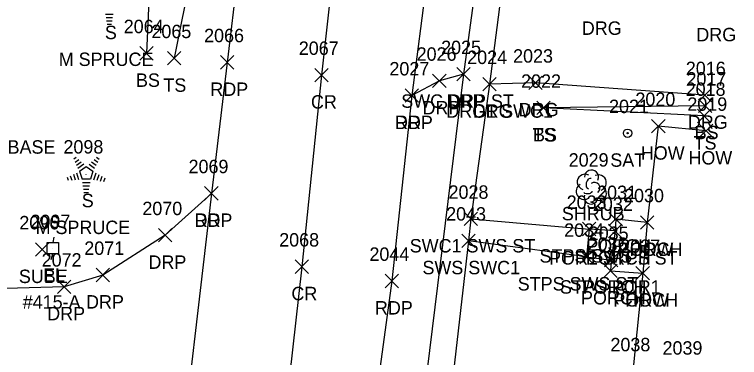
# Model space of a CAD drawing. Extents: x 1651305 to 1654558, y 539481 to 548441.
# Drawn here: x 1654335.1 to 1654443.3, y 544297.6 to 544348.7 of the extents above; entities that cross this region are included whole.
import ezdxf

# ---------------------------------------------------------------- set-up
doc = ezdxf.new("R2010")
doc.units = 0
for name, color, linetype in [('L_A', 7, 'Continuous'), ('L_C', 7, 'Continuous'), ('L_I', 7, 'Continuous'), ('L_TIC', 7, 'Continuous'), ('LANT', 7, 'Continuous'), ('LBC', 7, 'Continuous'), ('LBF', 7, 'Continuous'), ('LELB', 7, 'Continuous'), ('LSH', 7, 'Continuous'), ('LTC', 7, 'Continuous'), ('P_A', 7, 'Continuous'), ('P_I', 7, 'Continuous'), ('P_TIC', 7, 'Continuous'), ('PET', 7, 'Continuous'), ('PRC', 7, 'Continuous'), ('R_A', 7, 'Continuous'), ('R_I', 7, 'Continuous'), ('R_TIC', 7, 'Continuous'), ('RDG', 7, 'Continuous'), ('RDP', 7, 'Continuous'), ('RSW', 7, 'Continuous'), ('U_A', 7, 'Continuous'), ('U_C', 7, 'Continuous'), ('U_I', 7, 'Continuous'), ('U_TIC', 7, 'Continuous'), ('UEPT', 7, 'Continuous')]:
    doc.layers.add(name, color=color, linetype=linetype)

msp = doc.modelspace()

# ---------------------------------------------------------------- linework, layer by layer
at = {"layer": 'L_TIC'}
for points in [[(1654353.81, 544341.89), (1654355.81, 544343.89)], [(1654355.81, 544341.89), (1654353.81, 544343.89)], [(1654357.93, 544341.15), (1654359.93, 544343.15)], [(1654359.93, 544341.15), (1654357.93, 544343.15)], [(1654437.14, 544334.08), (1654439.14, 544336.08)], [(1654439.14, 544334.08), (1654437.14, 544336.08)], [(1654413.02, 544333.75), (1654415.02, 544335.75)], [(1654415.02, 544333.75), (1654413.02, 544335.75)], [(1654413.02, 544333.75), (1654415.02, 544335.75)], [(1654415.02, 544333.75), (1654413.02, 544335.75)], [(1654437.01, 544332.55), (1654439.01, 544334.55)], [(1654439.01, 544332.55), (1654437.01, 544334.55)], [(1654430.16, 544331.04), (1654432.16, 544333.04)], [(1654432.16, 544331.04), (1654430.16, 544333.04)], [(1654437.27, 544330.32), (1654439.27, 544332.32)], [(1654439.27, 544330.32), (1654437.27, 544332.32)], [(1654423.8, 544317.17), (1654425.8, 544319.17)], [(1654425.8, 544317.17), (1654423.8, 544319.17)], [(1654428.48, 544316.69), (1654430.48, 544318.69)], [(1654430.48, 544316.69), (1654428.48, 544318.69)], [(1654428.48, 544316.69), (1654430.48, 544318.69)], [(1654430.48, 544316.69), (1654428.48, 544318.69)], [(1654419.83, 544315.7), (1654421.83, 544317.7)], [(1654421.83, 544315.7), (1654419.83, 544317.7)], [(1654423.74, 544315.41), (1654425.74, 544317.41)], [(1654425.74, 544315.41), (1654423.74, 544317.41)], [(1654423.74, 544315.41), (1654425.74, 544317.41)], [(1654425.74, 544315.41), (1654423.74, 544317.41)], [(1654419.45, 544311.54), (1654421.45, 544313.54)], [(1654421.45, 544311.54), (1654419.45, 544313.54)], [(1654423.12, 544311.07), (1654425.12, 544313.07)], [(1654425.12, 544311.07), (1654423.12, 544313.07)], [(1654423.12, 544311.07), (1654425.12, 544313.07)], [(1654425.12, 544311.07), (1654423.12, 544313.07)], [(1654423.01, 544309.46), (1654425.01, 544311.46)], [(1654425.01, 544309.46), (1654423.01, 544311.46)], [(1654427.83, 544309.14), (1654429.83, 544311.14)], [(1654429.83, 544309.14), (1654427.83, 544311.14)], [(1654427.83, 544309.14), (1654429.83, 544311.14)], [(1654429.83, 544309.14), (1654427.83, 544311.14)]]:
    msp.add_lwpolyline(points, dxfattribs=at)
at = {"layer": 'LANT'}
for radius in [0.625, 0.0833]:
    msp.add_circle((1654426.58, 544330.98), radius, dxfattribs=at)
at = {"layer": 'LBC'}
msp.add_lwpolyline([(1654438.27, 544331.32), (1654431.16, 544332.04), (1654429.48, 544317.69), (1654428.83, 544310.14), (1654427.36, 544295.48), (1654435.14, 544294.98)], dxfattribs=at)
at = {"layer": 'LBF'}
for points in [[(1654429.48, 544317.69), (1654424.8, 544318.17), (1654424.74, 544316.41), (1654424.12, 544312.07), (1654424.01, 544310.46), (1654428.83, 544310.14)], [(1654424.74, 544316.41), (1654420.83, 544316.7), (1654420.45, 544312.54), (1654424.12, 544312.07)]]:
    msp.add_lwpolyline(points, dxfattribs=at)
at = {"layer": 'LELB'}
for points in [[(1654343.58, 544585.05), (1654350.34, 544565.29), (1654357.01, 544542.02), (1654364.12, 544503.19), (1654366.8, 544473.04), (1654369.36, 544432.64), (1654369.04, 544397.45), (1654364.12, 544367.94), (1654358.93, 544342.15)], [(1654331.96, 544545.97), (1654352.54, 544530.8), (1654354.98, 544503.34), (1654356.4, 544472.14), (1654357.75, 544432.79), (1654359.2, 544399.51), (1654355.94, 544368.56), (1654354.81, 544342.89)], [(1654438.14, 544335.08), (1654414.02, 544334.75)], [(1654438.01, 544333.55), (1654414.02, 544334.75)]]:
    msp.add_lwpolyline(points, dxfattribs=at)
at = {"layer": 'LSH'}
msp.add_line((1654421.14, 544323), (1654421.14, 544323), dxfattribs=at)
msp.add_line((1654421.14, 544323), (1654421.14, 544323), dxfattribs=at)
msp.add_arc((1654421.19, 544324.44), 1.05, 335.5272, 180.9563, dxfattribs=at)
for centre, major_axis, ratio, start_param, end_param in [((1654420.35, 544323.67), (1.21, -0.51), 0.895232, 1.570796, 4.712389), ((1654420.93, 544323.46), (-0.208, -0.792), 0.645439, 3.141593, 6.283185), ((1654422.18, 544323.58), (-1.14, -0.48), 0.949671, 1.570796, 4.712389), ((1654420.06, 544322.29), (0.58, -1.04), 0.959034, 3.141593, 6.283185), ((1654421.64, 544322.83), (-0.5, 0.667), 0.989748, 3.141593, 6.283185), ((1654422.14, 544322.17), (-1.09, 0.79), 0.841452, 1.570796, 4.712389), ((1654420.68, 544322.25), (-0.625, -0.083), 0.423636, 0, 3.141593), ((1654421.14, 544321.5), (0.26, 1.06), 0.942809, 1.570796, 4.712389)]:
    msp.add_ellipse(centre, major_axis=major_axis, ratio=ratio, start_param=start_param, end_param=end_param, dxfattribs=at)
at = {"layer": 'LTC'}
for p, q in [((1654349.85, 544348.67), (1654348.71, 544348.67)), ((1654349.77, 544348.17), (1654348.78, 544348.17)), ((1654349.68, 544347.67), (1654348.85, 544347.67)), ((1654349.6, 544347.17), (1654348.93, 544347.17)), ((1654343.96, 544327.16), (1654344.32, 544327.41)), ((1654347.36, 544327.4), (1654347.78, 544327.09)), ((1654344.17, 544326.69), (1654344.7, 544327.08)), ((1654344.38, 544326.23), (1654345.09, 544326.74)), ((1654344.59, 544325.76), (1654345.47, 544326.4)), ((1654346.25, 544326.35), (1654347.06, 544325.76)), ((1654346.62, 544326.7), (1654347.3, 544326.21)), ((1654346.99, 544327.05), (1654347.54, 544326.65)), ((1654344.36, 544325.09), (1654344.69, 544324.07)), ((1654344.82, 544325.31), (1654345.83, 544326.04)), ((1654344.82, 544325.31), (1654345.2, 544324.11)), ((1654345.83, 544326.04), (1654346.83, 544325.31)), ((1654346.83, 544325.31), (1654346.44, 544324.11)), ((1654347.26, 544325.04), (1654346.93, 544324)), ((1654343, 544324.44), (1654343.15, 544323.97)), ((1654343.45, 544324.65), (1654343.66, 544324)), ((1654343.91, 544324.87), (1654344.18, 544324.03)), ((1654346.44, 544324.11), (1654345.2, 544324.11)), ((1654347.71, 544324.79), (1654347.42, 544323.91)), ((1654348.15, 544324.54), (1654347.92, 544323.81)), ((1654348.6, 544324.29), (1654348.41, 544323.72)), ((1654346.4, 544323.61), (1654345.25, 544323.61)), ((1654346.31, 544323.11), (1654345.32, 544323.11)), ((1654346.23, 544322.61), (1654345.4, 544322.61)), ((1654346.15, 544322.11), (1654345.47, 544322.11))]:
    msp.add_line(p, q, dxfattribs=at)
at = {"layer": 'P_TIC'}
for points in [[(1654365.85, 544340.54), (1654367.85, 544342.54)], [(1654367.85, 544340.54), (1654365.85, 544342.54)], [(1654379.92, 544338.65), (1654381.92, 544340.65)], [(1654381.92, 544338.65), (1654379.92, 544340.65)], [(1654393.39, 544335.59), (1654395.39, 544337.59)], [(1654395.39, 544335.59), (1654393.39, 544337.59)], [(1654363.49, 544321.02), (1654365.49, 544323.02)], [(1654365.49, 544321.02), (1654363.49, 544323.02)], [(1654377, 544310.09), (1654379, 544312.09)], [(1654379, 544310.09), (1654377, 544312.09)], [(1654390.4, 544307.96), (1654392.4, 544309.96)], [(1654392.4, 544307.96), (1654390.4, 544309.96)]]:
    msp.add_lwpolyline(points, dxfattribs=at)
at = {"layer": 'PET'}
for points in [[(1654345.04, 544588.36), (1654350.59, 544607.19), (1654356.58, 544624.31), (1654366.69, 544597.7), (1654378.7, 544565.63), (1654388.8, 544536.02), (1654394.39, 544506.43), (1654399.12, 544481.01), (1654401.13, 544462.89), (1654401.53, 544436.35), (1654401.83, 544421.31), (1654397.37, 544359.7), (1654394.39, 544336.59), (1654391.4, 544308.96), (1654388.94, 544290.74), (1654386.84, 544274.06), (1654380.97, 544229.45), (1654377.75, 544202.91), (1654375.63, 544181.04), (1654372.19, 544149.75), (1654366.61, 544105.72), (1654362.8, 544072.79)], [(1654345.04, 544588.36), (1654352.84, 544566.03), (1654357.71, 544551.64), (1654360.67, 544540.21), (1654367.97, 544503.91), (1654371.19, 544473.22), (1654373.31, 544432.69), (1654372.37, 544396.63), (1654369.95, 544367.4), (1654366.85, 544341.54), (1654364.49, 544322.02), (1654359.18, 544276.5), (1654356.39, 544249.38), (1654353.63, 544216.56), (1654349.27, 544178.19), (1654347.29, 544164.71), (1654345.69, 544149.48), (1654340.92, 544117.48), (1654336.05, 544077.13)]]:
    msp.add_lwpolyline(points, dxfattribs=at)
at = {"layer": 'PRC'}
msp.add_lwpolyline([(1654350.59, 544607.19), (1654355.93, 544592.7), (1654363.68, 544570.63), (1654372.22, 544542.27), (1654380.24, 544505.39), (1654384.95, 544473.92), (1654386.82, 544433.75), (1654385.71, 544395.52), (1654383.86, 544366), (1654380.92, 544339.65), (1654378, 544311.09), (1654373.89, 544274.84), (1654369.01, 544231.01), (1654366.63, 544212.46), (1654362.44, 544177.97), (1654359.49, 544151.89), (1654354.07, 544107.93), (1654348.42, 544063.01)], dxfattribs=at)
at = {"layer": 'R_TIC'}
for points in [[(1654401.1, 544338.77), (1654403.1, 544340.77)], [(1654403.1, 544338.77), (1654401.1, 544340.77)], [(1654401.1, 544338.77), (1654403.1, 544340.77)], [(1654403.1, 544338.77), (1654401.1, 544340.77)], [(1654397.5, 544337.78), (1654399.5, 544339.78)], [(1654399.5, 544337.78), (1654397.5, 544339.78)], [(1654404.99, 544337.29), (1654406.99, 544339.29)], [(1654406.99, 544337.29), (1654404.99, 544339.29)], [(1654404.99, 544337.29), (1654406.99, 544339.29)], [(1654406.99, 544337.29), (1654404.99, 544339.29)], [(1654411.84, 544337.5), (1654413.84, 544339.5)], [(1654413.84, 544337.5), (1654411.84, 544339.5)], [(1654393.39, 544335.59), (1654395.39, 544337.59)], [(1654395.39, 544335.59), (1654393.39, 544337.59)], [(1654437.08, 544335.64), (1654439.08, 544337.64)], [(1654439.08, 544335.64), (1654437.08, 544337.64)], [(1654363.49, 544321.02), (1654365.49, 544323.02)], [(1654365.49, 544321.02), (1654363.49, 544323.02)], [(1654402.21, 544317.21), (1654404.21, 544319.21)], [(1654404.21, 544317.21), (1654402.21, 544319.21)], [(1654402.21, 544317.21), (1654404.21, 544319.21)], [(1654404.21, 544317.21), (1654402.21, 544319.21)], [(1654419.83, 544315.7), (1654421.83, 544317.7)], [(1654421.83, 544315.7), (1654419.83, 544317.7)], [(1654356.62, 544314.77), (1654358.62, 544316.77)], [(1654358.62, 544314.77), (1654356.62, 544316.77)], [(1654401.85, 544313.96), (1654403.85, 544315.96)], [(1654403.85, 544313.96), (1654401.85, 544315.96)], [(1654401.85, 544313.96), (1654403.85, 544315.96)], [(1654403.85, 544313.96), (1654401.85, 544315.96)], [(1654419.45, 544311.54), (1654421.45, 544313.54)], [(1654421.45, 544311.54), (1654419.45, 544313.54)], [(1654347.31, 544308.85), (1654349.31, 544310.85)], [(1654349.31, 544308.85), (1654347.31, 544310.85)], [(1654341.52, 544307.1), (1654343.52, 544309.1)], [(1654343.52, 544307.1), (1654341.52, 544309.1)]]:
    msp.add_lwpolyline(points, dxfattribs=at)
at = {"layer": 'RDG'}
msp.add_lwpolyline([(1654438.08, 544336.64), (1654412.84, 544338.5), (1654405.99, 544338.29)], dxfattribs=at)
at = {"layer": 'RDP'}
for points in [[(1654402.1, 544339.77), (1654398.5, 544338.78), (1654394.39, 544336.59)], [(1654364.49, 544322.02), (1654357.62, 544315.77), (1654348.31, 544309.85), (1654342.52, 544308.1), (1654304.14, 544306.98), (1654288.67, 544307.62)]]:
    msp.add_lwpolyline(points, dxfattribs=at)
at = {"layer": 'RSW'}
for points in [[(1654407.4, 544661.78), (1654407.29, 544658.87), (1654407.96, 544657.88), (1654443.27, 544654.59), (1654438.81, 544619.89), (1654433.56, 544580.17), (1654430.14, 544553.99), (1654428.03, 544537.28), (1654424.83, 544512.84), (1654419.77, 544473.61), (1654412.66, 544419.66), (1654404.12, 544354.77), (1654402.1, 544339.77), (1654395.49, 544286.06), (1654394.01, 544276.12), (1654388.39, 544229.58), (1654383.89, 544196.38), (1654382.2, 544184.33), (1654378.35, 544149.15), (1654372.36, 544105.49), (1654368.55, 544072.05)], [(1654433.77, 544447.32), (1654420.39, 544448.73), (1654416.3, 544419.47), (1654415.22, 544408.68), (1654412.66, 544388.62), (1654423.02, 544387.52), (1654429.58, 544386.83), (1654429.1, 544382.97), (1654422.69, 544383.71), (1654411.98, 544384.29), (1654408, 544354.11), (1654405.99, 544338.29), (1654403.21, 544318.21), (1654402.85, 544314.96), (1654399.43, 544285.11), (1654398.09, 544275.97), (1654392.33, 544231.26), (1654397.81, 544230.76), (1654412.22, 544229.3)], [(1654403.21, 544318.21), (1654420.83, 544316.7)], [(1654420.45, 544312.54), (1654402.85, 544314.96)]]:
    msp.add_lwpolyline(points, dxfattribs=at)
at = {"layer": 'U_TIC'}
for points in [[(1654338.24, 544312.65), (1654340.24, 544314.65)], [(1654340.24, 544312.65), (1654338.24, 544314.65)]]:
    msp.add_lwpolyline(points, dxfattribs=at)
at = {"layer": 'UEPT'}
for p, q in [((1654341.02, 544315.51), (1654340.85, 544314.67)), ((1654340.02, 544313.01), (1654340.02, 544314.67)), ((1654340.02, 544314.67), (1654341.68, 544314.67)), ((1654341.68, 544314.67), (1654341.68, 544313.01)), ((1654340.85, 544313.84), (1654340.85, 544313.84)), ((1654341.68, 544313.01), (1654340.02, 544313.01)), ((1654340.6, 544312.17), (1654340.85, 544313.01))]:
    msp.add_line(p, q, dxfattribs=at)

# ---------------------------------------------------------------- texts
at = {"layer": 'L_A'}
for s, p in [('S', (1654348.61, 544345)), ('BS', (1654353.25, 544337.89)), ('TS', (1654357.34, 544337.15)), ('TS', (1654412.43, 544329.75)), ('BS', (1654412.47, 544329.75)), ('BS', (1654436.58, 544330.08)), ('TS', (1654436.42, 544328.55)), ('HOW', (1654428.55, 544327.04)), ('HOW', (1654435.65, 544326.32)), ('SAT', (1654424, 544325.98)), ('S', (1654345.16, 544319.95)), ('SHRUB', (1654416.77, 544318)), ('PORCH', (1654420.42, 544313.17)), ('PORCH', (1654425.1, 544312.69)), ('HOW', (1654426.87, 544312.69)), ('STPS SWS', (1654413.44, 544311.7)), ('POR1 STPS ST', (1654414.86, 544311.41)), ('PORCH', (1654420.36, 544311.41)), ('STPS SWS ST', (1654410.19, 544307.54)), ('STPS POR1', (1654416.5, 544307.07)), ('PORCH', (1654419.74, 544307.07)), ('PORCH', (1654419.63, 544305.46)), ('PORCH', (1654424.45, 544305.14)), ('HOW', (1654426.22, 544305.14))]:
    msp.add_text(s, height=2, dxfattribs=at).set_placement(p)
at = {"layer": 'L_C'}
for s, p in [('M SPRUCE', (1654341.73, 544341)), ('STONE SIGN BASE', (1654316.86, 544327.93)), ('M SPRUCE', (1654338.27, 544315.95))]:
    msp.add_text(s, height=2, dxfattribs=at).set_placement(p)
at = {"layer": 'L_I'}
for s, p in [('2064', (1654351.42, 544345.89)), ('2065', (1654355.55, 544345.15)), ('2022', (1654410.69, 544337.75)), ('2022', (1654410.69, 544337.75)), ('2017', (1654435.36, 544338.08)), ('2018', (1654435.24, 544336.55)), ('2020', (1654427.74, 544335.04)), ('2021', (1654423.81, 544333.98)), ('2019', (1654435.49, 544334.32)), ('2098', (1654342.43, 544327.95)), ('2029', (1654417.79, 544326)), ('2031', (1654422.03, 544321.17)), ('2030', (1654426.05, 544320.69)), ('2030', (1654426.05, 544320.69)), ('2033', (1654417.49, 544319.7)), ('2032', (1654421.4, 544319.41)), ('2032', (1654421.4, 544319.41)), ('2034', (1654417.11, 544315.54)), ('2035', (1654420.78, 544315.07)), ('2035', (1654420.78, 544315.07)), ('2036', (1654420.62, 544313.46)), ('2037', (1654425.49, 544313.14)), ('2037', (1654425.49, 544313.14)), ('2038', (1654424.02, 544298.48)), ('2039', (1654431.79, 544297.98)), ('2039', (1654431.79, 544297.98))]:
    msp.add_text(s, height=2, dxfattribs=at).set_placement(p)
at = {"layer": 'LTC'}
msp.add_text('.', height=1.04, rotation=270, dxfattribs=at).set_placement((1654345.71, 544325.05))
at = {"layer": 'P_A'}
for s, p in [('RDP', (1654364.34, 544336.54)), ('CR', (1654379.35, 544334.65)), ('RDP', (1654391.88, 544331.59)), ('RDP', (1654361.98, 544317.02)), ('CR', (1654376.43, 544306.09)), ('RDP', (1654388.89, 544303.96))]:
    msp.add_text(s, height=2, dxfattribs=at).set_placement(p)
at = {"layer": 'P_I'}
for s, p in [('2066', (1654363.41, 544344.54)), ('2067', (1654377.53, 544342.65)), ('2027', (1654391.05, 544339.59)), ('2069', (1654361.09, 544325.02)), ('2068', (1654374.61, 544314.09)), ('2044', (1654388.07, 544311.96))]:
    msp.add_text(s, height=2, dxfattribs=at).set_placement(p)
at = {"layer": 'R_A'}
for s, p in [('DRG', (1654419.75, 544345.64)), ('DRG', (1654436.83, 544344.68)), ('SWC DRP ST', (1654392.82, 544334.77)), ('DRP', (1654399.59, 544334.77)), ('DRP', (1654395.99, 544333.78)), ('DRG1 SWC1', (1654399.54, 544333.29)), ('DRG', (1654403.48, 544333.29)), ('DRG', (1654410.33, 544333.5)), ('DRG', (1654435.57, 544331.64)), ('DRP', (1654391.88, 544331.59)), ('DRP', (1654361.98, 544317.02)), ('SWC1 SWS ST', (1654394.08, 544313.21)), ('SWC1 SWS ST', (1654394.08, 544313.21)), ('STPS SWS', (1654413.44, 544311.7)), ('DRP', (1654355.11, 544310.77)), ('SWS SWC1', (1654395.98, 544309.96)), ('SWS SWC1', (1654395.98, 544309.96)), ('STPS SWS ST', (1654410.19, 544307.54)), ('DRP', (1654345.8, 544304.85)), ('DRP', (1654340.01, 544303.1))]:
    msp.add_text(s, height=2, dxfattribs=at).set_placement(p)
at = {"layer": 'R_I'}
for s, p in [('2025', (1654398.76, 544342.77)), ('2025', (1654398.76, 544342.77)), ('2026', (1654395.11, 544341.78)), ('2023', (1654409.5, 544341.5)), ('2024', (1654402.65, 544341.29)), ('2024', (1654402.65, 544341.29)), ('2027', (1654391.05, 544339.59)), ('2016', (1654435.26, 544339.64)), ('2069', (1654361.09, 544325.02)), ('2028', (1654399.87, 544321.21)), ('2028', (1654399.87, 544321.21)), ('2070', (1654354.2, 544318.77)), ('2033', (1654417.49, 544319.7)), ('2043', (1654399.51, 544317.96)), ('2043', (1654399.51, 544317.96)), ('2034', (1654417.11, 544315.54)), ('2071', (1654345.54, 544312.85)), ('2072', (1654339.18, 544311.1))]:
    msp.add_text(s, height=2, dxfattribs=at).set_placement(p)
at = {"layer": 'U_A'}
for s, p in [('SUBE', (1654335.78, 544308.65)), ('EL', (1654339.39, 544308.84))]:
    msp.add_text(s, height=2, dxfattribs=at).set_placement(p)
at = {"layer": 'U_C'}
msp.add_text('#415-A', height=2, dxfattribs=at).set_placement((1654336.36, 544304.84))
at = {"layer": 'U_I'}
for s, p in [('2096', (1654335.85, 544316.65)), ('2097', (1654337.51, 544316.84))]:
    msp.add_text(s, height=2, dxfattribs=at).set_placement(p)

doc.saveas('drawing.dxf')
